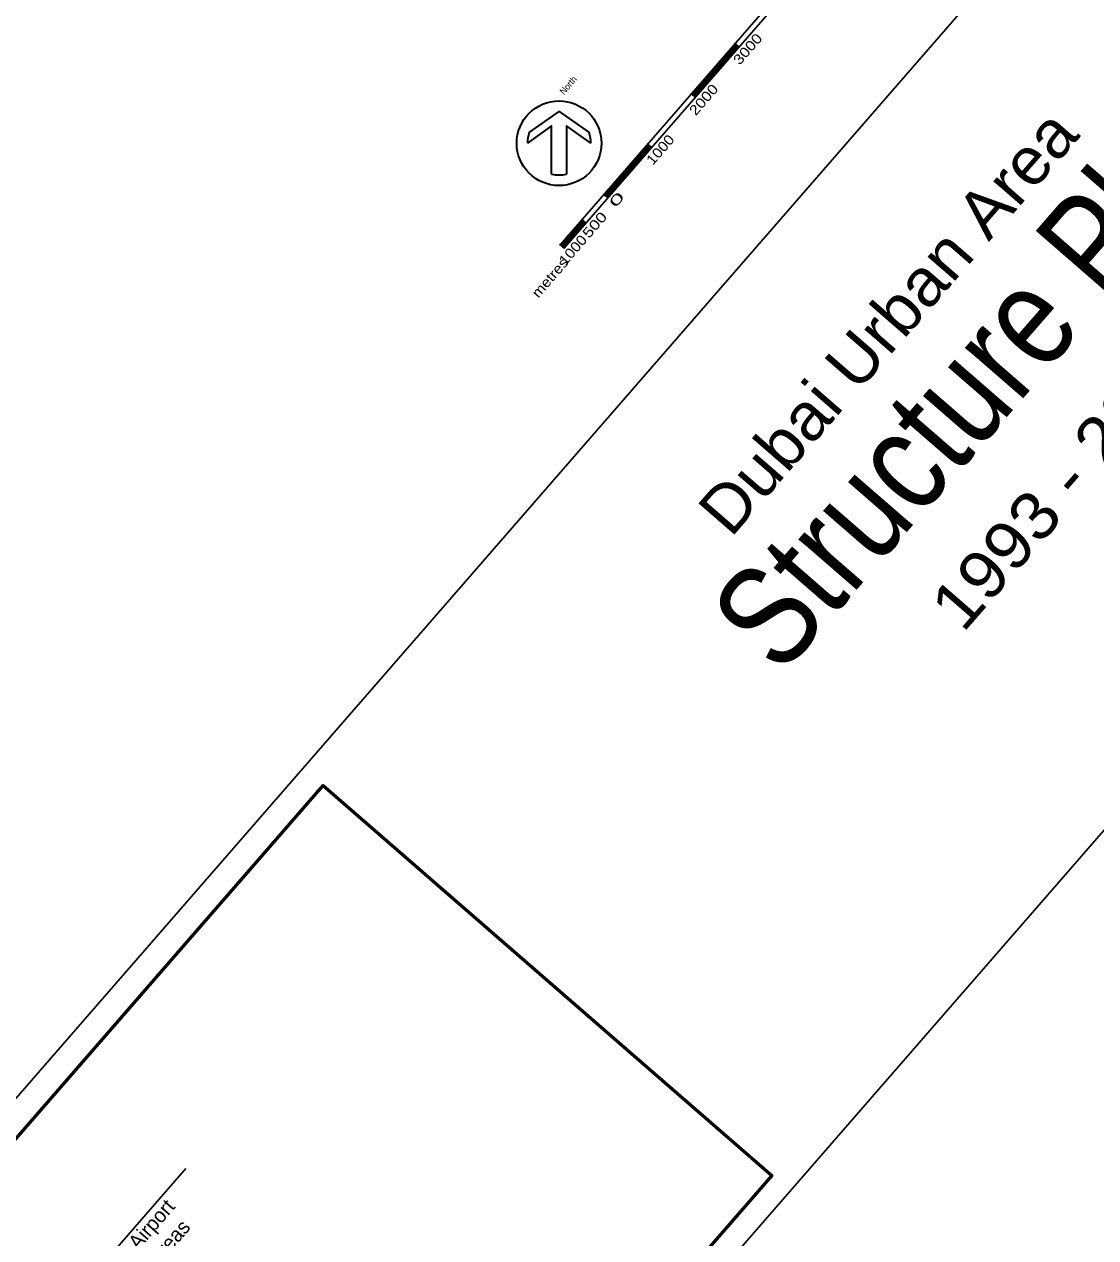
# Model space of a CAD drawing. Extents: x 290038 to 370218, y 2722677 to 2808586.
# Drawn here: x 345284 to 361355, y 2762800 to 2781010 of the extents above; entities that cross this region are included whole.
import ezdxf
from ezdxf.enums import TextEntityAlignment as Align

# ---------------------------------------------------------------- set-up
doc = ezdxf.new("R2010")
doc.units = 0
doc.header["$LTSCALE"] = 88
doc.layers.add('20', color=7, linetype='Continuous', lineweight=13)
doc.layers.add('63', color=7, linetype='Continuous', lineweight=35)

msp = doc.modelspace()

# ---------------------------------------------------------------- linework, layer by layer
at = {"layer": '20', "lineweight": 25}
msp.add_line((344122.07, 2759713.83), (347705.91, 2763836.57), dxfattribs=at)
msp.add_lwpolyline([(313980.4, 2729027.31), (362912.77, 2785317.56), (370218.38, 2778966.9), (321286.01, 2722676.64)], close=True, dxfattribs=at)
at = {"layer": '20', "lineweight": 35}
for points in [[(352857.23, 2779384.01), (353306.05, 2779700.94), (353754.87, 2779384.01)], [(353193.55, 2778761.9), (353193.55, 2779483.78), (352829.79, 2779226.92)], [(353782.3, 2779226.92), (353418.55, 2779483.78), (353418.55, 2778761.9)]]:
    msp.add_lwpolyline(points, dxfattribs=at)
at = {"layer": '20', "lineweight": 53}
msp.add_lwpolyline([(314544.71, 2729066.77), (349767.76, 2769586.26), (356498.65, 2763735.18), (321275.6, 2723215.69)], close=True, dxfattribs=at)
at = {"layer": '20', "lineweight": 35}
msp.add_circle((353306.05, 2779224.68), 635.01, dxfattribs=at)
for centre, radius, start, end in [((353306.07, 2779224.68), 476.28, 160.45491, 179.73023), ((353306.03, 2779224.68), 476.28, 0.26977, 19.54509), ((353306.05, 2779224.67), 476.26, 256.33664, 283.66336)]:
    msp.add_arc(centre, radius, start, end, dxfattribs=at)
at = {"layer": '63', "lineweight": 25}
for p, q in [((353321.51, 2777702.6), (360538.16, 2786004.41)), ((353381.89, 2777650.12), (360598.54, 2785951.92)), ((353389.44, 2777643.56), (353313.96, 2777709.17))]:
    msp.add_line(p, q, dxfattribs=at)
at = {"layer": '63'}
for p, q in [((355301.35, 2779956.6), (355957.41, 2780711.31)), ((355301.72, 2779956.27), (355957.78, 2780710.98)), ((355302.1, 2779955.94), (355958.16, 2780710.65)), ((355302.48, 2779955.61), (355958.54, 2780710.33)), ((355302.85, 2779955.29), (355958.92, 2780710)), ((355303.23, 2779954.96), (355959.29, 2780709.67)), ((355303.61, 2779954.63), (355959.67, 2780709.34)), ((355303.99, 2779954.3), (355960.05, 2780709.01)), ((355304.36, 2779953.97), (355960.42, 2780708.69)), ((355304.74, 2779953.65), (355960.8, 2780708.36)), ((355305.12, 2779953.32), (355961.18, 2780708.03)), ((355305.5, 2779952.99), (355961.56, 2780707.7)), ((355305.87, 2779952.66), (355961.93, 2780707.37)), ((355306.25, 2779952.33), (355962.31, 2780707.05)), ((355306.63, 2779952.01), (355962.69, 2780706.72)), ((355307.01, 2779951.68), (355963.07, 2780706.39)), ((355307.38, 2779951.35), (355963.44, 2780706.06)), ((355307.76, 2779951.02), (355963.82, 2780705.73)), ((355308.14, 2779950.69), (355964.2, 2780705.4)), ((355308.52, 2779950.37), (355964.58, 2780705.08)), ((355308.89, 2779950.04), (355964.95, 2780704.75)), ((355309.27, 2779949.71), (355965.33, 2780704.42)), ((355309.65, 2779949.38), (355965.71, 2780704.09)), ((355310.02, 2779949.05), (355966.09, 2780703.77)), ((355310.4, 2779948.73), (355966.46, 2780703.44)), ((355310.78, 2779948.4), (355966.84, 2780703.11)), ((355311.16, 2779948.07), (355967.22, 2780702.78)), ((355311.53, 2779947.74), (355967.59, 2780702.45)), ((355311.91, 2779947.41), (355967.97, 2780702.12)), ((355312.29, 2779947.09), (355968.35, 2780701.8)), ((355312.67, 2779946.76), (355968.73, 2780701.47)), ((355313.04, 2779946.43), (355969.1, 2780701.14)), ((355313.42, 2779946.1), (355969.48, 2780700.81)), ((355313.8, 2779945.77), (355969.86, 2780700.49)), ((355314.18, 2779945.45), (355970.24, 2780700.16)), ((355314.55, 2779945.12), (355970.61, 2780699.83)), ((355314.93, 2779944.79), (355970.99, 2780699.5)), ((355315.31, 2779944.46), (355971.37, 2780699.17)), ((355315.69, 2779944.13), (355971.75, 2780698.84)), ((355316.06, 2779943.8), (355972.12, 2780698.52)), ((355316.44, 2779943.48), (355972.5, 2780698.19)), ((355316.82, 2779943.15), (355972.88, 2780697.86)), ((355317.19, 2779942.82), (355973.26, 2780697.53)), ((355317.57, 2779942.49), (355973.63, 2780697.21)), ((355317.95, 2779942.17), (355974.01, 2780696.88)), ((355318.33, 2779941.84), (355974.39, 2780696.55)), ((355318.7, 2779941.51), (355974.76, 2780696.22)), ((355319.08, 2779941.18), (355975.14, 2780695.89)), ((355319.46, 2779940.85), (355975.52, 2780695.56)), ((355319.84, 2779940.52), (355975.9, 2780695.24)), ((355320.21, 2779940.2), (355976.27, 2780694.91)), ((355320.59, 2779939.87), (355976.65, 2780694.58)), ((355320.97, 2779939.54), (355977.03, 2780694.25)), ((355321.35, 2779939.21), (355977.41, 2780693.92)), ((355321.72, 2779938.89), (355977.78, 2780693.6)), ((355322.1, 2779938.56), (355978.16, 2780693.27)), ((355322.48, 2779938.23), (355978.54, 2780692.94)), ((355322.86, 2779937.9), (355978.92, 2780692.61)), ((355323.23, 2779937.57), (355979.29, 2780692.29)), ((355323.61, 2779937.25), (355979.67, 2780691.96)), ((355323.99, 2779936.92), (355980.05, 2780691.63)), ((355324.36, 2779936.59), (355980.43, 2780691.3)), ((355324.74, 2779936.26), (355980.8, 2780690.97)), ((355325.12, 2779935.93), (355981.18, 2780690.64)), ((355325.5, 2779935.6), (355981.56, 2780690.32)), ((355325.87, 2779935.28), (355981.93, 2780689.99)), ((355326.25, 2779934.95), (355982.31, 2780689.66)), ((355326.63, 2779934.62), (355982.69, 2780689.33)), ((355327.01, 2779934.29), (355983.07, 2780689)), ((355327.38, 2779933.96), (355983.44, 2780688.68)), ((355327.76, 2779933.64), (355983.82, 2780688.35)), ((355328.14, 2779933.31), (355984.2, 2780688.02)), ((355328.51, 2779932.98), (355984.58, 2780687.69)), ((355328.89, 2779932.65), (355984.95, 2780687.36)), ((355329.27, 2779932.32), (355985.33, 2780687.04)), ((355329.65, 2779932), (355985.71, 2780686.71)), ((355330.03, 2779931.67), (355986.08, 2780686.38)), ((355330.4, 2779931.34), (355986.46, 2780686.05)), ((355330.78, 2779931.01), (355986.84, 2780685.72)), ((355331.16, 2779930.69), (355987.22, 2780685.4)), ((355331.53, 2779930.36), (355987.59, 2780685.07)), ((355331.91, 2779930.03), (355987.97, 2780684.74)), ((355332.29, 2779929.7), (355988.35, 2780684.41)), ((355332.67, 2779929.37), (355988.73, 2780684.08)), ((355333.04, 2779929.04), (355989.1, 2780683.76)), ((355333.42, 2779928.72), (355989.48, 2780683.43)), ((355333.8, 2779928.39), (355989.86, 2780683.1)), ((355334.18, 2779928.06), (355990.24, 2780682.77)), ((355334.55, 2779927.73), (355990.61, 2780682.44)), ((355334.93, 2779927.4), (355990.99, 2780682.11)), ((355335.31, 2779927.08), (355991.37, 2780681.79)), ((355335.68, 2779926.75), (355991.75, 2780681.46)), ((355336.06, 2779926.42), (355992.12, 2780681.13)), ((355336.44, 2779926.09), (355992.5, 2780680.8)), ((355336.82, 2779925.76), (355992.88, 2780680.48)), ((355337.19, 2779925.44), (355993.25, 2780680.15)), ((355337.57, 2779925.11), (355993.63, 2780679.82)), ((355337.95, 2779924.78), (355994.01, 2780679.49)), ((355338.33, 2779924.45), (355994.39, 2780679.16)), ((355338.7, 2779924.12), (355994.76, 2780678.83)), ((353989.23, 2778447.18), (354645.29, 2779201.89)), ((353989.61, 2778446.85), (354645.66, 2779201.56)), ((353989.98, 2778446.52), (354646.04, 2779201.23)), ((353990.36, 2778446.2), (354646.42, 2779200.91)), ((353990.74, 2778445.87), (354646.8, 2779200.58)), ((353991.11, 2778445.54), (354647.17, 2779200.25)), ((353991.49, 2778445.21), (354647.55, 2779199.92)), ((353991.87, 2778444.88), (354647.93, 2779199.59)), ((353992.25, 2778444.56), (354648.31, 2779199.27)), ((353992.62, 2778444.23), (354648.68, 2779198.94)), ((353993, 2778443.9), (354649.06, 2779198.61)), ((353993.38, 2778443.57), (354649.44, 2779198.28)), ((353993.76, 2778443.25), (354649.82, 2779197.96)), ((353994.13, 2778442.92), (354650.19, 2779197.63)), ((353994.51, 2778442.59), (354650.57, 2779197.3)), ((353994.89, 2778442.26), (354650.95, 2779196.97)), ((353995.27, 2778441.93), (354651.33, 2779196.64)), ((353995.64, 2778441.6), (354651.7, 2779196.31)), ((353996.02, 2778441.28), (354652.08, 2779195.99)), ((353996.4, 2778440.95), (354652.46, 2779195.66)), ((353996.78, 2778440.62), (354652.83, 2779195.33)), ((353997.15, 2778440.29), (354653.21, 2779195)), ((353997.53, 2778439.96), (354653.59, 2779194.67)), ((353997.91, 2778439.64), (354653.97, 2779194.35)), ((353998.28, 2778439.31), (354654.34, 2779194.02)), ((353998.66, 2778438.98), (354654.72, 2779193.69)), ((353999.04, 2778438.65), (354655.1, 2779193.36)), ((353999.42, 2778438.32), (354655.48, 2779193.03)), ((353999.79, 2778438), (354655.85, 2779192.71)), ((354000.17, 2778437.67), (354656.23, 2779192.38)), ((354000.55, 2778437.34), (354656.61, 2779192.05)), ((354000.93, 2778437.01), (354656.99, 2779191.72)), ((354001.3, 2778436.68), (354657.36, 2779191.39)), ((354001.68, 2778436.36), (354657.74, 2779191.07)), ((354002.06, 2778436.03), (354658.12, 2779190.74)), ((354002.44, 2778435.7), (354658.5, 2779190.41)), ((354002.81, 2778435.37), (354658.87, 2779190.08)), ((354003.19, 2778435.04), (354659.25, 2779189.75)), ((354003.57, 2778434.72), (354659.63, 2779189.43)), ((354003.95, 2778434.39), (354660, 2779189.1)), ((354004.32, 2778434.06), (354660.38, 2779188.77)), ((354004.7, 2778433.73), (354660.76, 2779188.44)), ((354005.08, 2778433.4), (354661.14, 2779188.11)), ((354005.45, 2778433.07), (354661.51, 2779187.79)), ((354005.83, 2778432.75), (354661.89, 2779187.46)), ((354006.21, 2778432.42), (354662.27, 2779187.13)), ((354006.59, 2778432.09), (354662.65, 2779186.8)), ((354006.96, 2778431.76), (354663.02, 2779186.47)), ((354007.34, 2778431.44), (354663.4, 2779186.15)), ((354007.72, 2778431.11), (354663.78, 2779185.82)), ((354008.1, 2778430.78), (354664.16, 2779185.49)), ((354008.47, 2778430.45), (354664.53, 2779185.16)), ((354008.85, 2778430.12), (354664.91, 2779184.83)), ((354009.23, 2778429.79), (354665.29, 2779184.5)), ((354009.61, 2778429.47), (354665.66, 2779184.18)), ((354009.98, 2778429.14), (354666.04, 2779183.85)), ((354010.36, 2778428.81), (354666.42, 2779183.52)), ((354010.74, 2778428.48), (354666.8, 2779183.19)), ((354011.11, 2778428.16), (354667.17, 2779182.87)), ((354011.49, 2778427.83), (354667.55, 2779182.54)), ((354011.87, 2778427.5), (354667.93, 2779182.21)), ((354012.25, 2778427.17), (354668.31, 2779181.88)), ((354012.62, 2778426.84), (354668.68, 2779181.55)), ((354013, 2778426.51), (354669.06, 2779181.22)), ((354013.38, 2778426.19), (354669.44, 2779180.9)), ((354013.76, 2778425.86), (354669.82, 2779180.57)), ((354014.13, 2778425.53), (354670.19, 2779180.24)), ((354014.51, 2778425.2), (354670.57, 2779179.91)), ((354014.89, 2778424.87), (354670.95, 2779179.59)), ((354015.27, 2778424.55), (354671.33, 2779179.26)), ((354015.64, 2778424.22), (354671.7, 2779178.93)), ((354016.02, 2778423.89), (354672.08, 2779178.6)), ((354016.4, 2778423.56), (354672.46, 2779178.27)), ((354016.77, 2778423.23), (354672.83, 2779177.94)), ((354017.15, 2778422.91), (354673.21, 2779177.62)), ((354017.53, 2778422.58), (354673.59, 2779177.29)), ((354017.91, 2778422.25), (354673.97, 2779176.96)), ((354018.28, 2778421.92), (354674.34, 2779176.63)), ((354018.66, 2778421.59), (354674.72, 2779176.3)), ((354019.04, 2778421.27), (354675.1, 2779175.98)), ((354019.42, 2778420.94), (354675.48, 2779175.65)), ((354019.79, 2778420.61), (354675.85, 2779175.32)), ((354020.17, 2778420.28), (354676.23, 2779174.99)), ((354020.55, 2778419.96), (354676.61, 2779174.67)), ((354020.93, 2778419.63), (354676.99, 2779174.34)), ((354021.3, 2778419.3), (354677.36, 2779174.01)), ((354021.68, 2778418.97), (354677.74, 2779173.68)), ((354022.06, 2778418.64), (354678.12, 2779173.35)), ((354022.44, 2778418.31), (354678.5, 2779173.02)), ((354022.81, 2778417.99), (354678.87, 2779172.7)), ((354023.19, 2778417.66), (354679.25, 2779172.37)), ((354023.57, 2778417.33), (354679.63, 2779172.04)), ((354023.94, 2778417), (354680, 2779171.71)), ((354024.32, 2778416.67), (354680.38, 2779171.38)), ((354024.7, 2778416.35), (354680.76, 2779171.06)), ((354025.08, 2778416.02), (354681.14, 2779170.73)), ((354025.45, 2778415.69), (354681.51, 2779170.4)), ((354025.83, 2778415.36), (354681.89, 2779170.07)), ((354026.21, 2778415.03), (354682.27, 2779169.74)), ((354026.59, 2778414.71), (354682.65, 2779169.42)), ((353333.13, 2777692.51), (353661.16, 2778069.86)), ((353333.5, 2777692.18), (353661.53, 2778069.54)), ((353333.88, 2777691.85), (353661.91, 2778069.21)), ((353334.26, 2777691.52), (353662.29, 2778068.88)), ((353334.64, 2777691.19), (353662.67, 2778068.55)), ((353335.01, 2777690.87), (353663.04, 2778068.22)), ((353335.39, 2777690.54), (353663.42, 2778067.89)), ((353335.77, 2777690.21), (353663.8, 2778067.57)), ((353336.15, 2777689.88), (353664.18, 2778067.24)), ((353336.52, 2777689.56), (353664.55, 2778066.91)), ((353336.9, 2777689.23), (353664.93, 2778066.58)), ((353337.28, 2777688.9), (353665.31, 2778066.25)), ((353337.66, 2777688.57), (353665.68, 2778065.93)), ((353338.03, 2777688.24), (353666.06, 2778065.6)), ((353338.41, 2777687.92), (353666.44, 2778065.27)), ((353338.79, 2777687.59), (353666.82, 2778064.94)), ((353339.16, 2777687.26), (353667.19, 2778064.61)), ((353339.54, 2777686.93), (353667.57, 2778064.29)), ((353339.92, 2777686.6), (353667.95, 2778063.96)), ((353340.3, 2777686.27), (353668.33, 2778063.63)), ((353340.67, 2777685.95), (353668.7, 2778063.3)), ((353341.05, 2777685.62), (353669.08, 2778062.97)), ((353341.43, 2777685.29), (353669.46, 2778062.65)), ((353341.81, 2777684.96), (353669.84, 2778062.32)), ((353342.18, 2777684.63), (353670.21, 2778061.99)), ((353342.56, 2777684.31), (353670.59, 2778061.66)), ((353342.94, 2777683.98), (353670.97, 2778061.33)), ((353343.32, 2777683.65), (353671.34, 2778061)), ((353343.69, 2777683.32), (353671.72, 2778060.68)), ((353344.07, 2777682.99), (353672.1, 2778060.35)), ((353344.45, 2777682.67), (353672.48, 2778060.02)), ((353344.82, 2777682.34), (353672.85, 2778059.69)), ((353345.2, 2777682.01), (353673.23, 2778059.36)), ((353345.58, 2777681.68), (353673.61, 2778059.04)), ((353345.96, 2777681.35), (353673.99, 2778058.71)), ((353346.33, 2777681.03), (353674.36, 2778058.38)), ((353346.71, 2777680.7), (353674.74, 2778058.05)), ((353347.09, 2777680.37), (353675.12, 2778057.72)), ((353347.47, 2777680.04), (353675.5, 2778057.4)), ((353347.84, 2777679.71), (353675.87, 2778057.07)), ((353348.22, 2777679.39), (353676.25, 2778056.74)), ((353348.6, 2777679.06), (353676.63, 2778056.41)), ((353348.98, 2777678.73), (353677.01, 2778056.08)), ((353349.35, 2777678.4), (353677.38, 2778055.76)), ((353349.73, 2777678.07), (353677.76, 2778055.43)), ((353350.11, 2777677.75), (353678.14, 2778055.1)), ((353350.49, 2777677.42), (353678.51, 2778054.77)), ((353350.86, 2777677.09), (353678.89, 2778054.44)), ((353351.24, 2777676.76), (353679.27, 2778054.12)), ((353351.62, 2777676.43), (353679.65, 2778053.79)), ((353351.99, 2777676.11), (353680.02, 2778053.46)), ((353352.37, 2777675.78), (353680.4, 2778053.13)), ((353352.75, 2777675.45), (353680.78, 2778052.8)), ((353353.13, 2777675.12), (353681.16, 2778052.48)), ((353353.5, 2777674.79), (353681.53, 2778052.15)), ((353353.88, 2777674.47), (353681.91, 2778051.82)), ((353354.26, 2777674.14), (353682.29, 2778051.49)), ((353354.64, 2777673.81), (353682.67, 2778051.16)), ((353355.01, 2777673.48), (353683.04, 2778050.84)), ((353355.39, 2777673.15), (353683.42, 2778050.51)), ((353355.77, 2777672.83), (353683.8, 2778050.18)), ((353356.15, 2777672.5), (353684.18, 2778049.85)), ((353356.52, 2777672.17), (353684.55, 2778049.52)), ((353356.9, 2777671.84), (353684.93, 2778049.2)), ((353357.28, 2777671.51), (353685.31, 2778048.87)), ((353357.66, 2777671.19), (353685.68, 2778048.54)), ((353358.03, 2777670.86), (353686.06, 2778048.21)), ((353358.41, 2777670.53), (353686.44, 2778047.88)), ((353358.79, 2777670.2), (353686.82, 2778047.56)), ((353359.16, 2777669.87), (353687.19, 2778047.23)), ((353359.54, 2777669.55), (353687.57, 2778046.9)), ((353359.92, 2777669.22), (353687.95, 2778046.57)), ((353360.3, 2777668.89), (353688.33, 2778046.24)), ((353360.67, 2777668.56), (353688.7, 2778045.92)), ((353361.05, 2777668.23), (353689.08, 2778045.59)), ((353361.43, 2777667.9), (353689.46, 2778045.26)), ((353361.81, 2777667.58), (353689.84, 2778044.93)), ((353362.18, 2777667.25), (353690.21, 2778044.6)), ((353362.56, 2777666.92), (353690.59, 2778044.28)), ((353362.94, 2777666.59), (353690.97, 2778043.95)), ((353363.31, 2777666.26), (353691.35, 2778043.62)), ((353363.69, 2777665.94), (353691.72, 2778043.29)), ((353364.07, 2777665.61), (353692.1, 2778042.96)), ((353364.45, 2777665.28), (353692.48, 2778042.64)), ((353364.83, 2777664.95), (353692.85, 2778042.31)), ((353365.2, 2777664.62), (353693.23, 2778041.98)), ((353365.58, 2777664.3), (353693.61, 2778041.65)), ((353365.96, 2777663.97), (353693.99, 2778041.32)), ((353366.33, 2777663.64), (353694.36, 2778041)), ((353366.71, 2777663.31), (353694.74, 2778040.67)), ((353367.09, 2777662.98), (353695.12, 2778040.34)), ((353367.47, 2777662.66), (353695.5, 2778040.01)), ((353367.84, 2777662.33), (353695.87, 2778039.68)), ((353368.22, 2777662), (353696.25, 2778039.35)), ((353368.6, 2777661.67), (353696.63, 2778039.03)), ((353368.98, 2777661.34), (353697, 2778038.7)), ((353369.35, 2777661.02), (353697.38, 2778038.37)), ((353369.73, 2777660.69), (353697.76, 2778038.04)), ((353370.11, 2777660.36), (353698.14, 2778037.71)), ((353370.48, 2777660.03), (353698.51, 2778037.39))]:
    msp.add_line(p, q, dxfattribs=at)
at = {"layer": '63', "lineweight": 13}
for p, q in [((356013.67, 2780662.4), (355938.2, 2780728)), ((355357.61, 2779907.69), (355282.14, 2779973.29)), ((354701.55, 2779152.98), (354626.08, 2779218.58)), ((354045.49, 2778398.27), (353970.02, 2778463.87)), ((353717.46, 2778020.92), (353641.99, 2778086.52))]:
    msp.add_line(p, q, dxfattribs=at)
for points in [[(355338.74, 2779924.09), (355994.81, 2780678.8), (355957.07, 2780711.6), (355301.01, 2779956.89)], [(354026.63, 2778414.67), (354682.69, 2779169.38), (354644.95, 2779202.18), (353988.89, 2778447.47)], [(353370.57, 2777659.96), (353698.6, 2778037.31), (353660.86, 2778070.12), (353332.83, 2777692.76)]]:
    msp.add_lwpolyline(points, close=True, dxfattribs=at)

# ---------------------------------------------------------------- texts
at = {"layer": '20'}
for s, height, width, p in [('Structure Plan', 1507, 0.85, (360189.92, 2775307.87)), ('Dubai Urban Area', 712.5, 1.05, (358508.26, 2776312.12)), ('1993 - 2012', 712.5, 1.1, (361198.16, 2773973.82))]:
    msp.add_text(s, height=height, rotation=49, dxfattribs=dict(at, width=width)).set_placement(p, align=Align.CENTER)
for s, p in [('Potential Relocation of Airport, Airport', (344325.06, 2759535.12)), ('Related and General Industrial Areas', (344609.32, 2759288.01))]:
    msp.add_text(s, height=220.4, rotation=49, dxfattribs=at).set_placement(p)
at = {"layer": '63'}
for s, height, width, p in [('3000', 150, 1.2, (356191.05, 2780590.21)), ('North', 100, 0.95, (353480.96, 2780062.57)), ('2000', 150, 1.2, (355530.15, 2779829.96)), ('1000', 150, 1.15, (354880.34, 2779079.29)), ('0', 150, 2, (354225.41, 2778330.39)), ('500', 150, 1.3, (353895.91, 2777949.45)), ('1000', 150, 1.15, (353568.91, 2777573.28)), ('metres', 150, 1.15, (353225.88, 2777159.3))]:
    msp.add_text(s, height=height, rotation=49, dxfattribs=dict(at, width=width)).set_placement(p, align=Align.CENTER)

doc.saveas('drawing.dxf')
